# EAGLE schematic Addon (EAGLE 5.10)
COPYRIGHT: © Leo-Andres Hofmann; LICENSE: CC-BY-SA 3.0; PROJEKT: Vorlage; REVISION: 1.0; TEXT-5: Platine: 75mm x 85mm

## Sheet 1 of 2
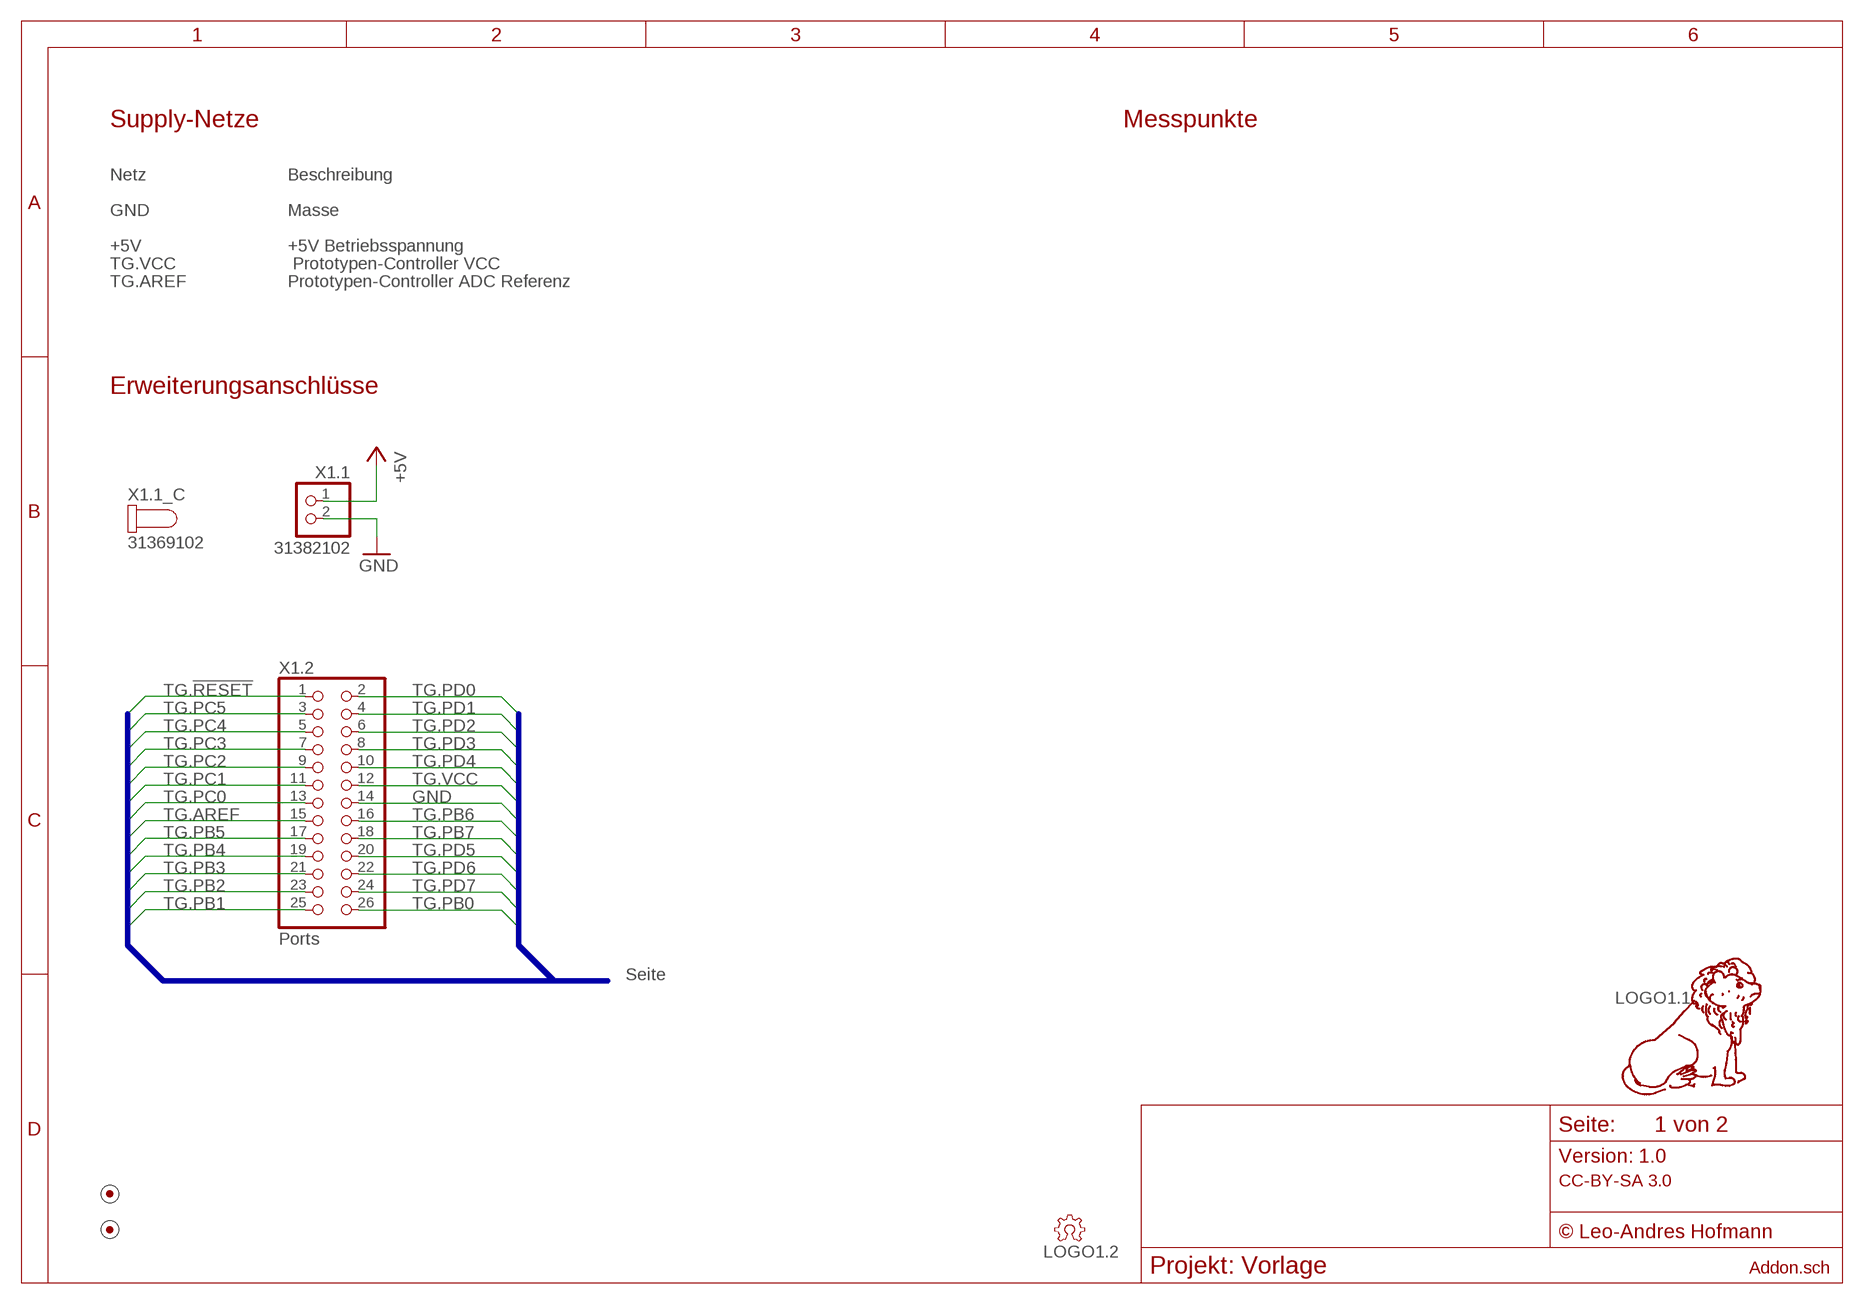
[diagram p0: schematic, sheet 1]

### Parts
LOGO1.1  LOGO-15MM-TPLACE  [15MM-TPLACE]
LOGO1.2  OSHW-3MM-TOP  [OSHW-3MM-TOP]
MARK1  FIDUCIAL-1.0/CREAM  [FIDUCIAL-1MM/CREAM]
MARK2  FIDUCIAL-1.0/CREAM  [FIDUCIAL-1MM/CREAM]
X1.1  31382102  1PIN-2-31382102  [31382102]
X1.2  Ports  PINHD-2X13  [2X13]

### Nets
+5V: X1.1.1
GND: X1.1.2 X1.2.14
TG.!RESET: X1.2.1
TG.AREF: X1.2.15
TG.PB0: X1.2.26
TG.PB1: X1.2.25
TG.PB2: X1.2.23
TG.PB3: X1.2.21
TG.PB4: X1.2.19
TG.PB5: X1.2.17
TG.PB6: X1.2.16
TG.PB7: X1.2.18
TG.PC0: X1.2.13
TG.PC1: X1.2.11
TG.PC2: X1.2.9
TG.PC3: X1.2.7
TG.PC4: X1.2.5
TG.PC5: X1.2.3
TG.PD0: X1.2.2
TG.PD1: X1.2.4
TG.PD2: X1.2.6
TG.PD3: X1.2.8
TG.PD4: X1.2.10
TG.PD5: X1.2.20
TG.PD6: X1.2.22
TG.PD7: X1.2.24
TG.VCC: X1.2.12

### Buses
TG:GND,TG.VCC,TG.!RESET,TG.AREF,TG.PB0,TG.PB1,TG.PB2,TG.PB3,TG.PB4,TG.PB5,TG.PB6,TG.PB7,TG.PC0,TG.PC1,TG.PC2,TG.PC3,TG.PC4,TG.PC5,TG.PD0,TG.PD1,TG.PD2,TG.PD3,TG.PD4,TG.PD5,TG.PD6,TG.PD7

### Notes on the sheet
- Supply-Netze | Messpunkte
- Netz | Beschreibung
- GND | Masse
- +5V | +5V Betriebsspannung
- TG.VCC | Prototypen-Controller VCC
- TG.AREF | Prototypen-Controller ADC Referenz
- Erweiterungsanschlüsse
- Seite

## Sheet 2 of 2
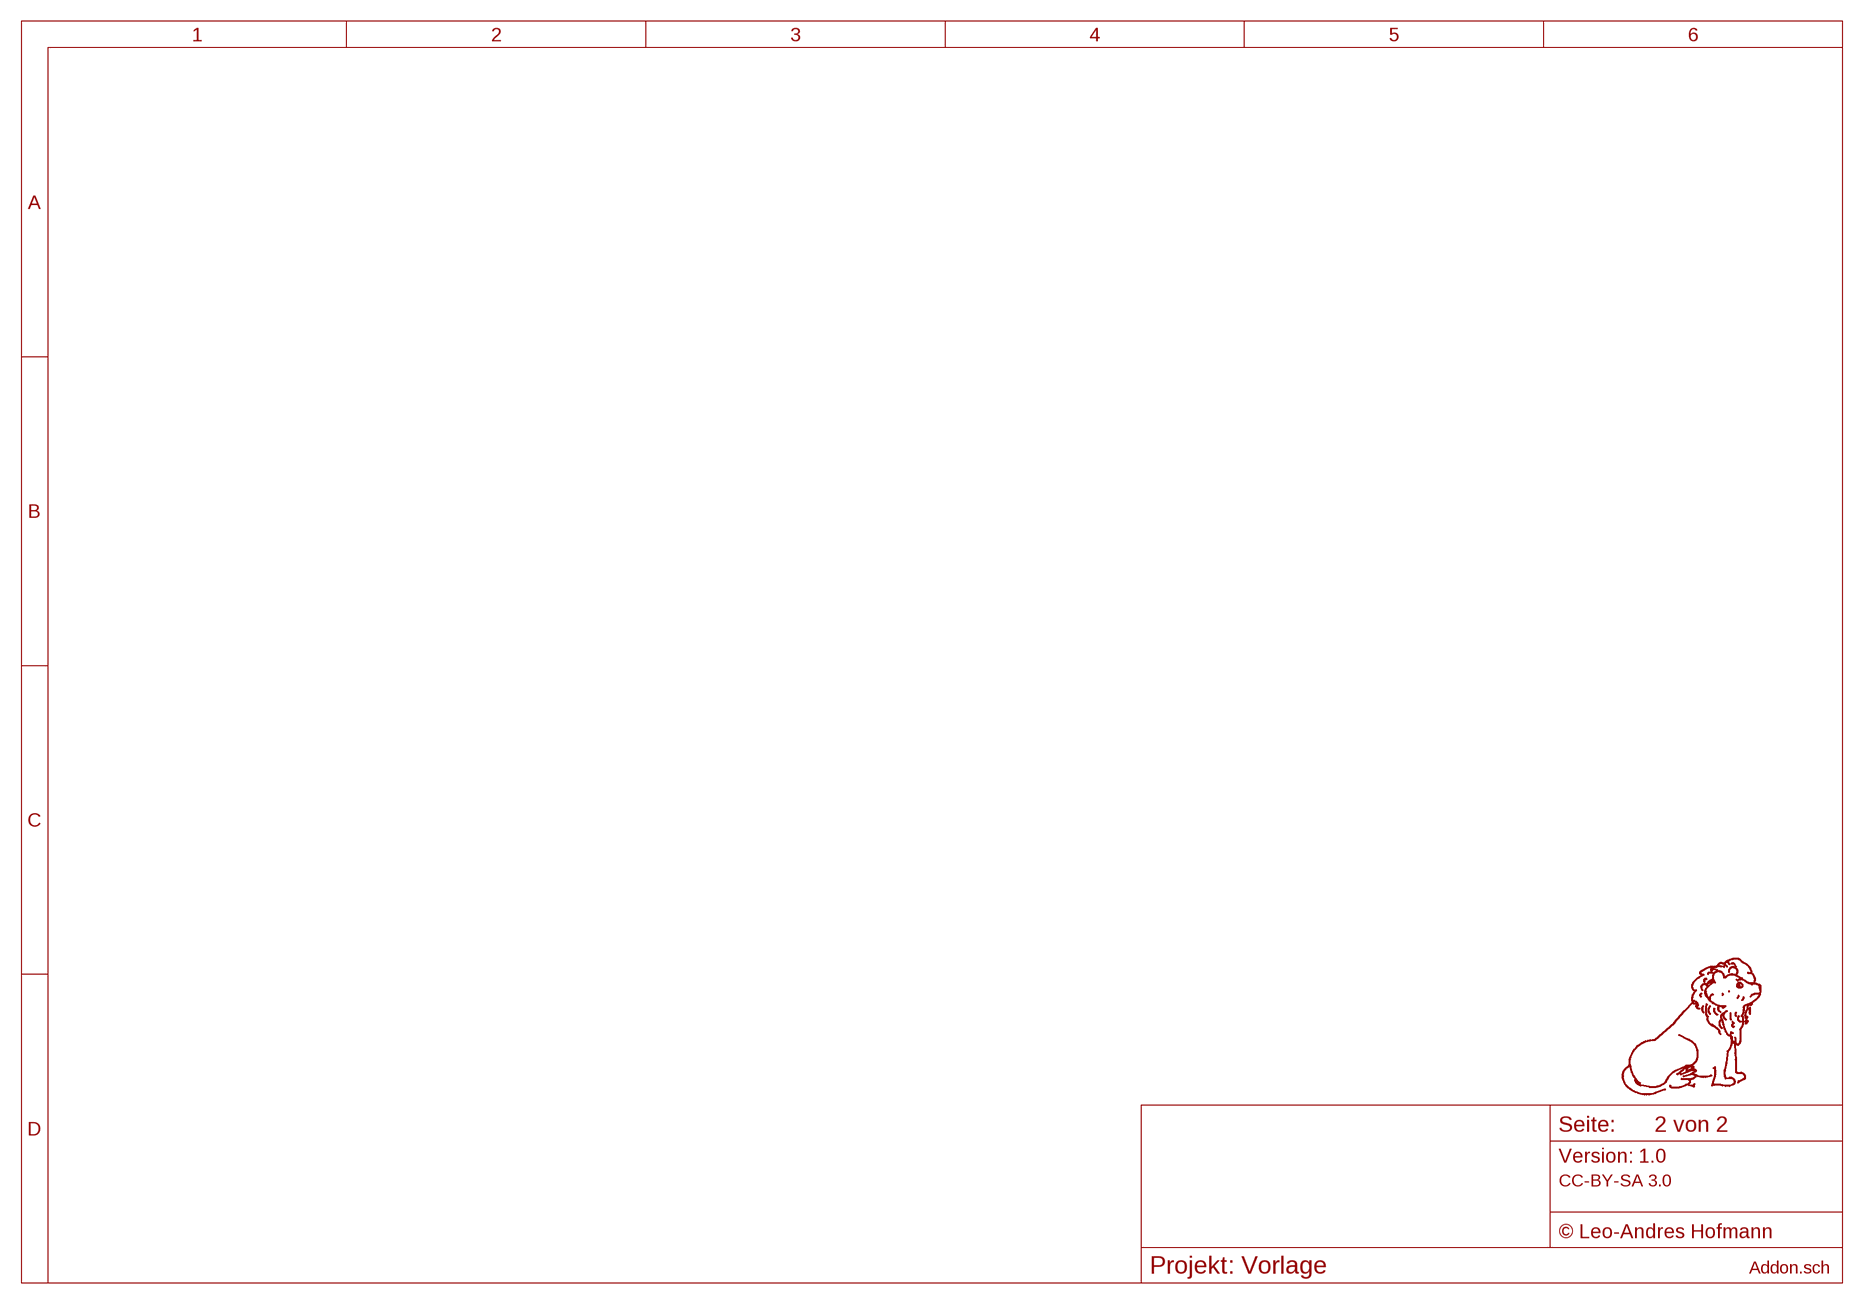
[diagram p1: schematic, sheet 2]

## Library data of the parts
LOGO1.1 = leo_misc-logo:LOGO: leo-andres.de PCB Logo
LOGO1.2 = leo_misc-logo:OSHW: OSHW Logo
MARK1 MARK2 = leo_misc-logo:FIDUCIAL: Fiducial
X1.1 = leo_con-ria:1PIN-2: 1 Pin Header, 2 Pole
X1.2 = pinhead:PINHD-2X13: PIN HEADER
